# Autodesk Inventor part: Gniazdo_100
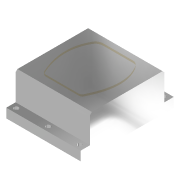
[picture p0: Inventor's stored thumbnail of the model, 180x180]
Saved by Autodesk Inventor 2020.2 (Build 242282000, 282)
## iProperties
Created: 2010-12
Part Number: Gniazdo_100
Document SubType Name: Modeling
Designer: F.Stasiak
Density: 1 g/cm^3
Material: Ogólny
Appearance: Chrom
Manager: www.cadconsulting.pl
Company: Fabian Stasiak CAD Consulting
Author: F.Stasiak
Subject: Zbiór ćwiczeń. Autodesk Inventor 2020. Kurs podstawowy
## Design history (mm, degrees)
sketch "Szkic1"
  geometry: L1 (-200, -250)-(200, -250); L2 (200, -250)-(200, 250); L3 (200, 250)-(-200, 250); L4 (-200, 250)-(-200, -250); 3 further points
  constraints: 8 end point, 2 midpoint, 2 parallel, 1 horizontal, 1 horizontal alignment, 1 perpendicular, 1 vertical alignment
  dimensions: "d0" = 400 distance of L3.end L2.end; "d1" = 500 distance of L2.end L1.end
extrude "Wyciągnięcie proste1" new body sketch "Szkic1" distance "d2" = 200; taper "d3" = 0 deg
sketch "Szkic2"
  geometry: L1 (-200, 500)-(-200, 0) reference; L2 (0, 0)-(-200, 0) reference; L3 (0, 500)-(-200, 500) reference; L4 (-50, 500)-(-50, 450); L5 (-50, 450)-(-200, 450); L6 (-200, 50)-(-50, 50); L7 (-50, 50)-(-50, 0); 1 further point
  constraints: 8 end point, 4 point on line, 3 perpendicular, 1 collinear, 1 parallel
  dimensions: "d29" = 50 distance of L4.start L4.end; "d30" = 150 distance of L4.end L5.end; "d31" = 50 distance of L6.end L7.end (= d29)
extrude "Wyciągnięcie proste2" cut sketch "Szkic2" extent not by distance; stored distance "d32" = 200; taper "d33" = 0 deg
sketch "Szkic3"
  geometry: L1 (-400, 0)-(-400, 50) reference; L2 (0, 50)-(0, 0) reference; L3 (-400, 25)-(0, 25); 4 further points
  constraints: 3 midpoint, 2 end point, 2 point on line
  dimensions: "d34" = 30 distance from line of L1 point (-370, 25); "d35" = 30 distance from line of L2 point (-30, 25) (= d34)
hole "Hole1" sketch "Szkic3" at (-370, 25), (-30, 25), (-200, 25) diameter "d36" = 15.5; stored, may be unused: countersink angle "d40" = 82 deg, drill point angle "d42" = 118 deg; dims "d37" = 6, "d38" = 24, "d39" = 15, "d41" = 8
mirror "Odbicie lustrzane1"
feature "Złożony1"
chamfer "Faza1" distance "d43" = 10; stored, may be unused: second distance "d44" = 2, angle "d45" = 45 deg
node "Bryła1"
body "Srf4"
other parameters: "d5" = 0.5, "d6" = 2, "d7" = 0
